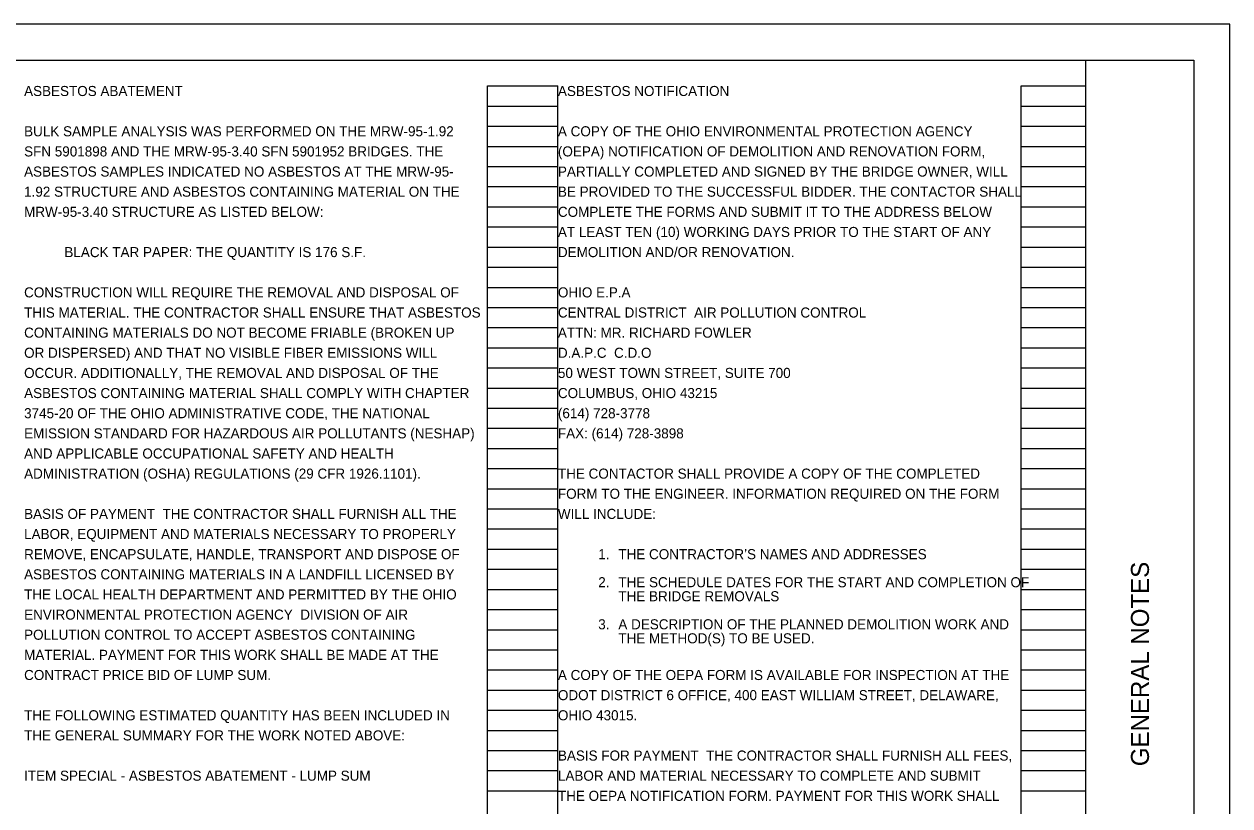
# Model space of a CAD drawing. Extents: x 0 to 34, y 0 to 22.
# Drawn here: x 17.24 to 34, y 11.13 to 22 of the extents above; entities that cross this region are included whole.
import ezdxf

# ---------------------------------------------------------------- set-up
doc = ezdxf.new("R2010")
doc.units = 0
for name, color, linetype in [('SH_Border', 7, 'Continuous'), ('SH_Cut_Line', 7, 'Continuous'), ('SH_Data', 7, 'Continuous'), ('SH_Text', 7, 'Continuous')]:
    doc.layers.add(name, color=color, linetype=linetype)

msp = doc.modelspace()

# ---------------------------------------------------------------- linework, layer by layer
at = {"layer": 'SH_Border'}
msp.add_line((32, 0.5), (32, 21.5), dxfattribs=at)
msp.add_lwpolyline([(1.5, 21.5), (33.5, 21.5), (33.5, 0.5), (1.5, 0.5)], close=True, dxfattribs=at)
at = {"layer": 'SH_Cut_Line'}
msp.add_lwpolyline([(0, 0), (34, 0), (34, 22), (0, 22)], close=True, dxfattribs=at)
at = {"layer": 'SH_Data'}
for p, q in [((23.68, 0.98), (23.68, 21.14)), ((23.68, 21.14), (24.66, 21.14)), ((24.66, 0.98), (24.66, 21.14)), ((31.1, 0.98), (31.1, 21.14)), ((31.1, 21.14), (32, 21.14)), ((32, 0.98), (32, 21.14)), ((23.68, 20.86), (24.66, 20.86)), ((31.1, 20.86), (32, 20.86)), ((23.68, 20.58), (24.66, 20.58)), ((31.1, 20.58), (32, 20.58)), ((23.68, 20.3), (24.66, 20.3)), ((31.1, 20.3), (32, 20.3)), ((23.68, 20.02), (24.66, 20.02)), ((31.1, 20.02), (32, 20.02)), ((23.68, 19.74), (24.66, 19.74)), ((31.1, 19.74), (32, 19.74)), ((23.68, 19.46), (24.66, 19.46)), ((31.1, 19.46), (32, 19.46)), ((23.68, 19.18), (24.66, 19.18)), ((31.1, 19.18), (32, 19.18)), ((23.68, 18.9), (24.66, 18.9)), ((31.1, 18.9), (32, 18.9)), ((23.68, 18.62), (24.66, 18.62)), ((31.1, 18.62), (32, 18.62)), ((23.68, 18.34), (24.66, 18.34)), ((31.1, 18.34), (32, 18.34)), ((23.68, 18.06), (24.66, 18.06)), ((31.1, 18.06), (32, 18.06)), ((23.68, 17.78), (24.66, 17.78)), ((31.1, 17.78), (32, 17.78)), ((23.68, 17.5), (24.66, 17.5)), ((31.1, 17.5), (32, 17.5)), ((23.68, 17.22), (24.66, 17.22)), ((31.1, 17.22), (32, 17.22)), ((23.68, 16.94), (24.66, 16.94)), ((31.1, 16.94), (32, 16.94)), ((23.68, 16.66), (24.66, 16.66)), ((31.1, 16.66), (32, 16.66)), ((23.68, 16.38), (24.66, 16.38)), ((31.1, 16.38), (32, 16.38)), ((23.68, 16.1), (24.66, 16.1)), ((31.1, 16.1), (32, 16.1)), ((23.68, 15.82), (24.66, 15.82)), ((31.1, 15.82), (32, 15.82)), ((23.68, 15.54), (24.66, 15.54)), ((31.1, 15.54), (32, 15.54)), ((23.68, 15.26), (24.66, 15.26)), ((31.1, 15.26), (32, 15.26)), ((23.68, 14.98), (24.66, 14.98)), ((31.1, 14.98), (32, 14.98)), ((23.68, 14.7), (24.66, 14.7)), ((31.1, 14.7), (32, 14.7)), ((23.68, 14.42), (24.66, 14.42)), ((31.1, 14.42), (32, 14.42)), ((23.68, 14.14), (24.66, 14.14)), ((31.1, 14.14), (32, 14.14)), ((23.68, 13.86), (24.66, 13.86)), ((31.1, 13.86), (32, 13.86)), ((23.68, 13.58), (24.66, 13.58)), ((31.1, 13.58), (32, 13.58)), ((23.68, 13.3), (24.66, 13.3)), ((31.1, 13.3), (32, 13.3)), ((23.68, 13.02), (24.66, 13.02)), ((31.1, 13.02), (32, 13.02)), ((23.68, 12.74), (24.66, 12.74)), ((31.1, 12.74), (32, 12.74)), ((23.68, 12.46), (24.66, 12.46)), ((31.1, 12.46), (32, 12.46)), ((23.68, 12.18), (24.66, 12.18)), ((31.1, 12.18), (32, 12.18)), ((23.68, 11.9), (24.66, 11.9)), ((31.1, 11.9), (32, 11.9)), ((23.68, 11.62), (24.66, 11.62)), ((31.1, 11.62), (32, 11.62)), ((23.68, 11.34), (24.66, 11.34)), ((31.1, 11.34), (32, 11.34))]:
    msp.add_line(p, q, dxfattribs=at)

# ---------------------------------------------------------------- texts
msp.add_text('GENERAL NOTES', height=0.25, rotation=90, dxfattribs=at).set_placement((32.875, 11.682))
at = {"layer": 'SH_Text'}
for s, p in [('ASBESTOS ABATEMENT', (17.24, 21)), ('ASBESTOS NOTIFICATION', (24.66, 21)), ('BULK SAMPLE ANALYSIS WAS PERFORMED ON THE MRW-95-1.92 ', (17.24, 20.44)), ('A COPY OF THE OHIO ENVIRONMENTAL PROTECTION AGENCY ', (24.66, 20.44)), ('SFN 5901898 AND THE MRW-95-3.40 SFN 5901952 BRIDGES. THE ', (17.24, 20.16)), ('(OEPA) NOTIFICATION OF DEMOLITION AND RENOVATION FORM, ', (24.66, 20.16)), ('ASBESTOS SAMPLES INDICATED NO ASBESTOS AT THE MRW-95-', (17.24, 19.88)), ('PARTIALLY COMPLETED AND SIGNED BY THE BRIDGE OWNER, WILL ', (24.66, 19.88)), ('1.92 STRUCTURE AND ASBESTOS CONTAINING MATERIAL ON THE ', (17.24, 19.6)), ('BE PROVIDED TO THE SUCCESSFUL BIDDER. THE CONTACTOR SHALL ', (24.66, 19.6)), ('MRW-95-3.40 STRUCTURE AS LISTED BELOW:', (17.24, 19.32)), ('COMPLETE THE FORMS AND SUBMIT IT TO THE ADDRESS BELOW ', (24.66, 19.32)), ('AT LEAST TEN (10) WORKING DAYS PRIOR TO THE START OF ANY ', (24.66, 19.04)), ('BLACK TAR PAPER: THE QUANTITY IS 176 S.F.', (17.8, 18.76)), ('DEMOLITION AND/OR RENOVATION.', (24.66, 18.76)), ('CONSTRUCTION WILL REQUIRE THE REMOVAL AND DISPOSAL OF ', (17.24, 18.2)), ('OHIO E.P.A', (24.66, 18.2)), ('THIS MATERIAL. THE CONTRACTOR SHALL ENSURE THAT ASBESTOS ', (17.24, 17.92)), ('CENTRAL DISTRICT  AIR POLLUTION CONTROL', (24.66, 17.92)), ('CONTAINING MATERIALS DO NOT BECOME FRIABLE (BROKEN UP ', (17.24, 17.64)), ('ATTN: MR. RICHARD FOWLER', (24.66, 17.64)), ('OR DISPERSED) AND THAT NO VISIBLE FIBER EMISSIONS WILL ', (17.24, 17.36)), ('D.A.P.C  C.D.O', (24.66, 17.36)), ('OCCUR. ADDITIONALLY, THE REMOVAL AND DISPOSAL OF THE ', (17.24, 17.08)), ('50 WEST TOWN STREET, SUITE 700', (24.66, 17.08)), ('ASBESTOS CONTAINING MATERIAL SHALL COMPLY WITH CHAPTER ', (17.24, 16.8)), ('COLUMBUS, OHIO 43215', (24.66, 16.8)), ('3745-20 OF THE OHIO ADMINISTRATIVE CODE, THE NATIONAL ', (17.24, 16.52)), ('(614) 728-3778', (24.66, 16.52)), ('EMISSION STANDARD FOR HAZARDOUS AIR POLLUTANTS (NESHAP) ', (17.24, 16.24)), ('FAX: (614) 728-3898', (24.66, 16.24)), ('AND APPLICABLE OCCUPATIONAL SAFETY AND HEALTH ', (17.24, 15.96)), ('ADMINISTRATION (OSHA) REGULATIONS (29 CFR 1926.1101).', (17.24, 15.68)), ('THE CONTACTOR SHALL PROVIDE A COPY OF THE COMPLETED ', (24.66, 15.68)), ('FORM TO THE ENGINEER. INFORMATION REQUIRED ON THE FORM ', (24.66, 15.4)), ('BASIS OF PAYMENT  THE CONTRACTOR SHALL FURNISH ALL THE ', (17.24, 15.12)), ('WILL INCLUDE:', (24.66, 15.12)), ('LABOR, EQUIPMENT AND MATERIALS NECESSARY TO PROPERLY ', (17.24, 14.84)), ('REMOVE, ENCAPSULATE, HANDLE, TRANSPORT AND DISPOSE OF ', (17.24, 14.56)), ('1.', (25.22, 14.56)), ('THE CONTRACTOR’S NAMES AND ADDRESSES ', (25.5, 14.56)), ('ASBESTOS CONTAINING MATERIALS IN A LANDFILL LICENSED BY ', (17.24, 14.28)), ('2.', (25.22, 14.17)), ('THE SCHEDULE DATES FOR THE START AND COMPLETION OF ', (25.5, 14.17)), ('THE LOCAL HEALTH DEPARTMENT AND PERMITTED BY THE OHIO ', (17.24, 14)), ('THE BRIDGE REMOVALS', (25.5, 13.975)), ('ENVIRONMENTAL PROTECTION AGENCY  DIVISION OF AIR ', (17.24, 13.72)), ('POLLUTION CONTROL TO ACCEPT ASBESTOS CONTAINING ', (17.24, 13.44)), ('3.', (25.22, 13.585)), ('A DESCRIPTION OF THE PLANNED DEMOLITION WORK AND ', (25.5, 13.585)), ('THE METHOD(S) TO BE USED.', (25.5, 13.39)), ('MATERIAL. PAYMENT FOR THIS WORK SHALL BE MADE AT THE ', (17.24, 13.16)), ('CONTRACT PRICE BID OF LUMP SUM.', (17.24, 12.88)), ('A COPY OF THE OEPA FORM IS AVAILABLE FOR INSPECTION AT THE ', (24.66, 12.88)), ('ODOT DISTRICT 6 OFFICE, 400 EAST WILLIAM STREET, DELAWARE, ', (24.66, 12.6)), ('THE FOLLOWING ESTIMATED QUANTITY HAS BEEN INCLUDED IN ', (17.24, 12.32)), ('OHIO 43015.', (24.66, 12.32)), ('THE GENERAL SUMMARY FOR THE WORK NOTED ABOVE:', (17.24, 12.04)), ('BASIS FOR PAYMENT  THE CONTRACTOR SHALL FURNISH ALL FEES, ', (24.66, 11.76)), ('ITEM SPECIAL - ASBESTOS ABATEMENT - LUMP SUM', (17.24, 11.48)), ('LABOR AND MATERIAL NECESSARY TO COMPLETE AND SUBMIT ', (24.66, 11.48)), ('THE OEPA NOTIFICATION FORM. PAYMENT FOR THIS WORK SHALL ', (24.66, 11.2))]:
    msp.add_text(s, height=0.14, dxfattribs=at).set_placement(p)

doc.saveas('drawing.dxf')
